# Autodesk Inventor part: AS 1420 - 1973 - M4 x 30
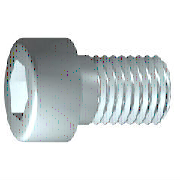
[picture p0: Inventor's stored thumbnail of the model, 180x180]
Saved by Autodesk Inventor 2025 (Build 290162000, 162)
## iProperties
Created: 2024-01
Part Number: AS 1420 - 1973 - M4 x 30
Material: Acciaio, Dolce
Description: Viti con esagono incassato metriche ISO
Document SubType Name: Modeling
Standard: AS 1420 - 1973
Designer: 18907419
Standards Organization: AS
Language: it-IT
Size Designation: M4 x 30
Categories: <MemberInstance><Categories><Category DisplayName="Elementi di fissaggio" InternalName="e4da775c-781d-43d5-af7c-5136215cf5a6" Mnemonic="FSTN"><Category DisplayN
Density: 7.85 g/cm^3
Appearance: Semilucidato
IsCustomPart: 0
Author: 18907419
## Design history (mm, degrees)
workplane "Work Plane1"
fillet "Fillet2" dims "d30" = 0.1 (= R)
revolve "Corpo" stored, may be unused: angle "d10" = 90 deg
sketch "Schizzo2"
  geometry: L1 (0, -4.9)-(0, 4.9) reference; L2 (-4.9, 0)-(4.9, 0) reference; L3 (1.732, 0)-(0.866, -1.5); L4 (0.866, -1.5)-(-0.866, -1.5); L5 (-0.866, -1.5)-(-1.732, 0); L6 (-1.732, 0)-(-0.866, 1.5); L7 (-0.866, 1.5)-(0.866, 1.5); L8 (0.866, 1.5)-(1.732, 0); 2 further points
  constraints: 12 end point, 1 coincident, 1 horizontal alignment, 1 point on line, 12 other
extrude "Intaglio" join sketch "Schizzo2" stored distance "d11" = 10; taper "d12" = 0 deg
body "Solid1"
fillet "Raccordo1" dims "d17" = 0.4 (= RR)
feature "Filettatura" dims "d13" = 14 (= GEL), "d14" = 0
chamfer "Smusso1" distance "d15" = 0.42941 (= -0.5 x SPD + 0.5 x GD); stored, may be unused: second distance "d16" = 0.42941 (= GUL), angle "d27" = 45 deg
sketch "Schizzo1"
  geometry: L1 (-1, 0)-(30, 0); L2 (30, 0)-(30, 2); L3 (30, 2)-(16, 2); L4 (16, 2)-(15.57, 2); L5 (15.57, 2)-(0, 2); L6 (0, 2)-(0, 3.5); L7 (0, 3.5)-(-4, 3.5); L8 (-4, 3.5)-(-4, 1.732); L9 (-4, 1.732)-(-2, 1.732); L10 (-2, 1.732)-(-1, 0); L11 (-10.8, 0)-(36.8, 0) reference; L12 (0, -0.7)-(0, 4.2) reference; L13 (16, 2)-(0, 2)
  constraints: 22 end point, 6 parallel, 2 collinear, 2 perpendicular, 1 horizontal, 1 point on line
  dimensions: "d1" = 14 distance from line of L3.end L2 (= GEL); "d2" = 0.42952 distance of L4.end L3.end (computed from GAL); "d3" = 4 distance between parallel lines of L8 L6 (= KOH); "d4" = 2 distance of L8.end L9.end (= INTI); "d5" = 60 deg angle of L10 L1; "d6" = 4 diameter of L3 L1 (= GD); "d7" = 4 diameter of L5 L1 (= BDM); "d8" = 3.4641 diameter of L9 L1 (= 1.1547 x SW); "d9" = 7 diameter of L7 L1 (= KOD); "d26" = 30 distance between parallel lines of L12 L2 (= NLG)
other parameters: "GD" = 4 (= NND) [user parameter; used in 2 equation terms], "NLG" = 30 [user parameter; used in 1 equation term], "GEL" = 14 [user parameter; used in 2 equation terms], "KOD" = 7 [user parameter; used in 1 equation term], "KOH" = 4 (= NND) [user parameter; used in 1 equation term], "INTI" = 2 [user parameter; used in 1 equation term], "GAL" = 0.42941 (= 0.61345 x PTC) [user parameter; used in 1 equation term], "GUL" = 0.42941 (= 0.61345 x PTC) [user parameter; used in 1 equation term], "BDM" = 4 (= NND) [user parameter; used in 1 equation term], "SW" = 3 [user parameter; used in 2 equation terms], "RR" = 0.4 (= 0.1 x NND) [user parameter; used in 1 equation term], "SPD" = 3.14117 (= NND - 1.2269 x PTC) [user parameter; used in 1 equation term], "d19" = 0, "d28" = 0, "d29" = 0, "R" = 0.1 [user parameter; used in 1 equation term], "PHH" = 0.13 [user parameter], "GD1" = 3.14117 (= THREADDIA - 1.2269 x PTC) [user parameter], "THREADDIA" = 4 [user parameter; used in 1 equation term], "FAWI" = 45 deg [user parameter], "TPU" = 14.28571 (computed from PTC) [user parameter], "PTC" = 0.7 [user parameter; used in 5 equation terms], "KOH1" = 3.6 [user parameter], "NND" = 4 [user parameter; used in 5 equation terms], "TOA" = 30 deg [user parameter], "E0" = 3.465 (= 1.155 x SW) [user parameter]
